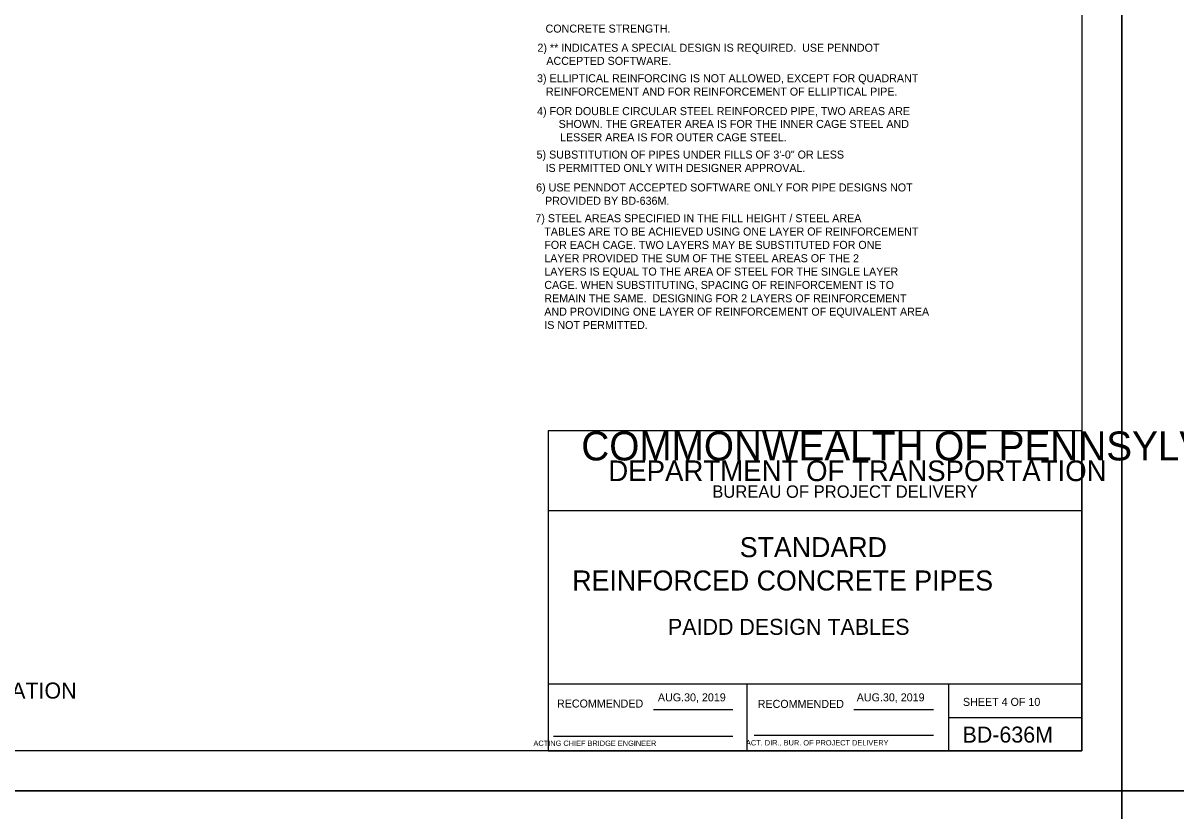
# Model space of a CAD drawing. Extents: x -22562 to -18409, y 3991 to 7171.
# Drawn here: x -19955.7 to -19523.6, y 5765.9 to 6061.2 of the extents above; entities that cross this region are included whole.
import ezdxf

# ---------------------------------------------------------------- set-up
doc = ezdxf.new("R2010")
doc.units = 0
for name, color, linetype in [('1', 7, 'Continuous'), ('2', 7, 'Continuous'), ('4', 7, 'Continuous'), ('63', 7, 'Continuous'), ('PLT-BNDY', 7, 'Continuous')]:
    doc.layers.add(name, color=color, linetype=linetype)

msp = doc.modelspace()

# ---------------------------------------------------------------- linework, layer by layer
at = {"layer": '2'}
for p, q in [((-19558.85, 6352.37), (-19558.85, 5788.37)), ((-19558.85, 5908.37), (-19758.85, 5908.37)), ((-19758.85, 5908.37), (-19758.85, 5788.37)), ((-19558.85, 5788.37), (-19558.85, 5908.37)), ((-19558.85, 5878.37), (-19758.85, 5878.37)), ((-19558.85, 5813.37), (-19758.85, 5813.37)), ((-19684.35, 5788.37), (-19684.35, 5813.37)), ((-19608.85, 5813.37), (-19608.85, 5788.37)), ((-19719.38, 5803.87), (-19689.62, 5803.87)), ((-19644.38, 5803.87), (-19614.47, 5803.87)), ((-19608.85, 5800.87), (-19558.85, 5800.87)), ((-19756.85, 5793.87), (-19689.62, 5793.87)), ((-19681.72, 5794.24), (-19614.47, 5794.24)), ((-19558.85, 5788.37), (-20344.85, 5788.37)), ((-19758.85, 5788.37), (-19558.85, 5788.37))]:
    msp.add_line(p, q, dxfattribs=at)
at = {"layer": '63'}
msp.add_line((-19543.85, 5773.37), (-19543.85, 5773.37), dxfattribs=at)
at = {"layer": 'PLT-BNDY'}
for points in [[(-20384.85, 6367.37), (-19543.85, 6367.37), (-19543.85, 5773.37), (-20384.85, 5773.37)], [(-19543.85, 6367.37), (-18702.85, 6367.37), (-18702.85, 5773.37), (-19543.85, 5773.37)], [(-20384.85, 5773.37), (-19543.85, 5773.37), (-19543.85, 5179.37), (-20384.85, 5179.37)], [(-19543.85, 5773.37), (-18702.85, 5773.37), (-18702.85, 5179.37), (-19543.85, 5179.37)]]:
    msp.add_lwpolyline(points, close=True, dxfattribs=at)

# ---------------------------------------------------------------- texts
at = {"layer": '1'}
for s, p in [('6) USE PENNDOT ACCEPTED SOFTWARE ONLY FOR PIPE DESIGNS NOT', (-19763.4, 5998.06)), ('   PROVIDED BY BD-636M.', (-19763.4, 5993.05)), ('7) STEEL AREAS SPECIFIED IN THE FILL HEIGHT / STEEL AREA', (-19763.68, 5986.54)), ('   TABLES ARE TO BE ACHIEVED USING ONE LAYER OF REINFORCEMENT', (-19763.68, 5981.54)), ('   FOR EACH CAGE. TWO LAYERS MAY BE SUBSTITUTED FOR ONE', (-19763.68, 5976.53)), ('   LAYER PROVIDED THE SUM OF THE STEEL AREAS OF THE 2', (-19763.68, 5971.53)), ('   LAYERS IS EQUAL TO THE AREA OF STEEL FOR THE SINGLE LAYER', (-19763.68, 5966.52)), ('   CAGE. WHEN SUBSTITUTING, SPACING OF REINFORCEMENT IS TO', (-19763.68, 5961.52)), ('   REMAIN THE SAME.  DESIGNING FOR 2 LAYERS OF REINFORCEMENT ', (-19763.68, 5956.51)), ('   AND PROVIDING ONE LAYER OF REINFORCEMENT OF EQUIVALENT AREA', (-19763.68, 5951.51)), ('   IS NOT PERMITTED.', (-19763.68, 5946.5))]:
    msp.add_text(s, height=3, dxfattribs=at).set_placement(p)
at = {"layer": '2'}
for s, height, p in [('5) SUBSTITUTION OF PIPES UNDER FILLS OF 3\'-0" OR LESS', 3, (-19763.22, 6010.38)), ('   IS PERMITTED ONLY WITH DESIGNER APPROVAL.                                                                                   ', 3, (-19763.22, 6005.37)), ('COMMONWEALTH OF PENNSYLVANIA', 10.8525, (-19746.47, 5897.24)), ('DEPARTMENT OF TRANSPORTATION', 7.7332, (-19736.35, 5889.49)), ('BUREAU OF PROJECT DELIVERY', 4.6493, (-19697.39, 5883.24)), ('STANDARD', 7.5, (-19687.1, 5860.99)), ('REINFORCED CONCRETE PIPES', 7.5, (-19749.85, 5848.49)), ('PAIDD DESIGN TABLES', 6, (-19713.97, 5831.87)), ('DESIGN TABLES FOR CIRCULAR PIPES - TYPE A STANDARD INSTALLATION', 6, (-20228.97, 5807.99)), ('AUG.30, 2019', 3, (-19717.76, 5806.94)), ('AUG.30, 2019', 3, (-19643.25, 5806.94)), ('SHEET 4 OF 10', 3, (-19603.44, 5805.24)), ('BD-636M', 6, (-19603.6, 5791.49)), ('       ACTING CHIEF BRIDGE ENGINEER', 2.0002, (-19769.76, 5790.24)), ('   ACT. DIR., BUR. OF PROJECT DELIVERY', 2.0002, (-19687.05, 5790.42))]:
    msp.add_text(s, height=height, dxfattribs=at).set_placement(p)
for p in [(-19755.58, 5804.62), (-19680.36, 5804.49)]:
    msp.add_text('RECOMMENDED', height=3, rotation=360, dxfattribs=at).set_placement(p)
at = {"layer": '4'}
for s, p in [('   CONCRETE STRENGTH.', (-19763.21, 6057.6)), ('2) ** INDICATES A SPECIAL DESIGN IS REQUIRED.  USE PENNDOT', (-19762.91, 6050.42)), ('   ACCEPTED SOFTWARE.', (-19762.91, 6045.5)), ('3) ELLIPTICAL REINFORCING IS NOT ALLOWED, EXCEPT FOR QUADRANT', (-19763.06, 6038.99)), ('   REINFORCEMENT AND FOR REINFORCEMENT OF ELLIPTICAL PIPE.', (-19763.06, 6033.98)), ('4) FOR DOUBLE CIRCULAR STEEL REINFORCED PIPE, TWO AREAS ARE', (-19763.03, 6026.66)), ('SHOWN. THE GREATER AREA IS FOR THE INNER CAGE STEEL AND', (-19754.96, 6021.86)), ('LESSER AREA IS FOR OUTER CAGE STEEL.', (-19754.43, 6016.85))]:
    msp.add_text(s, height=3, dxfattribs=at).set_placement(p)

doc.saveas('drawing.dxf')
